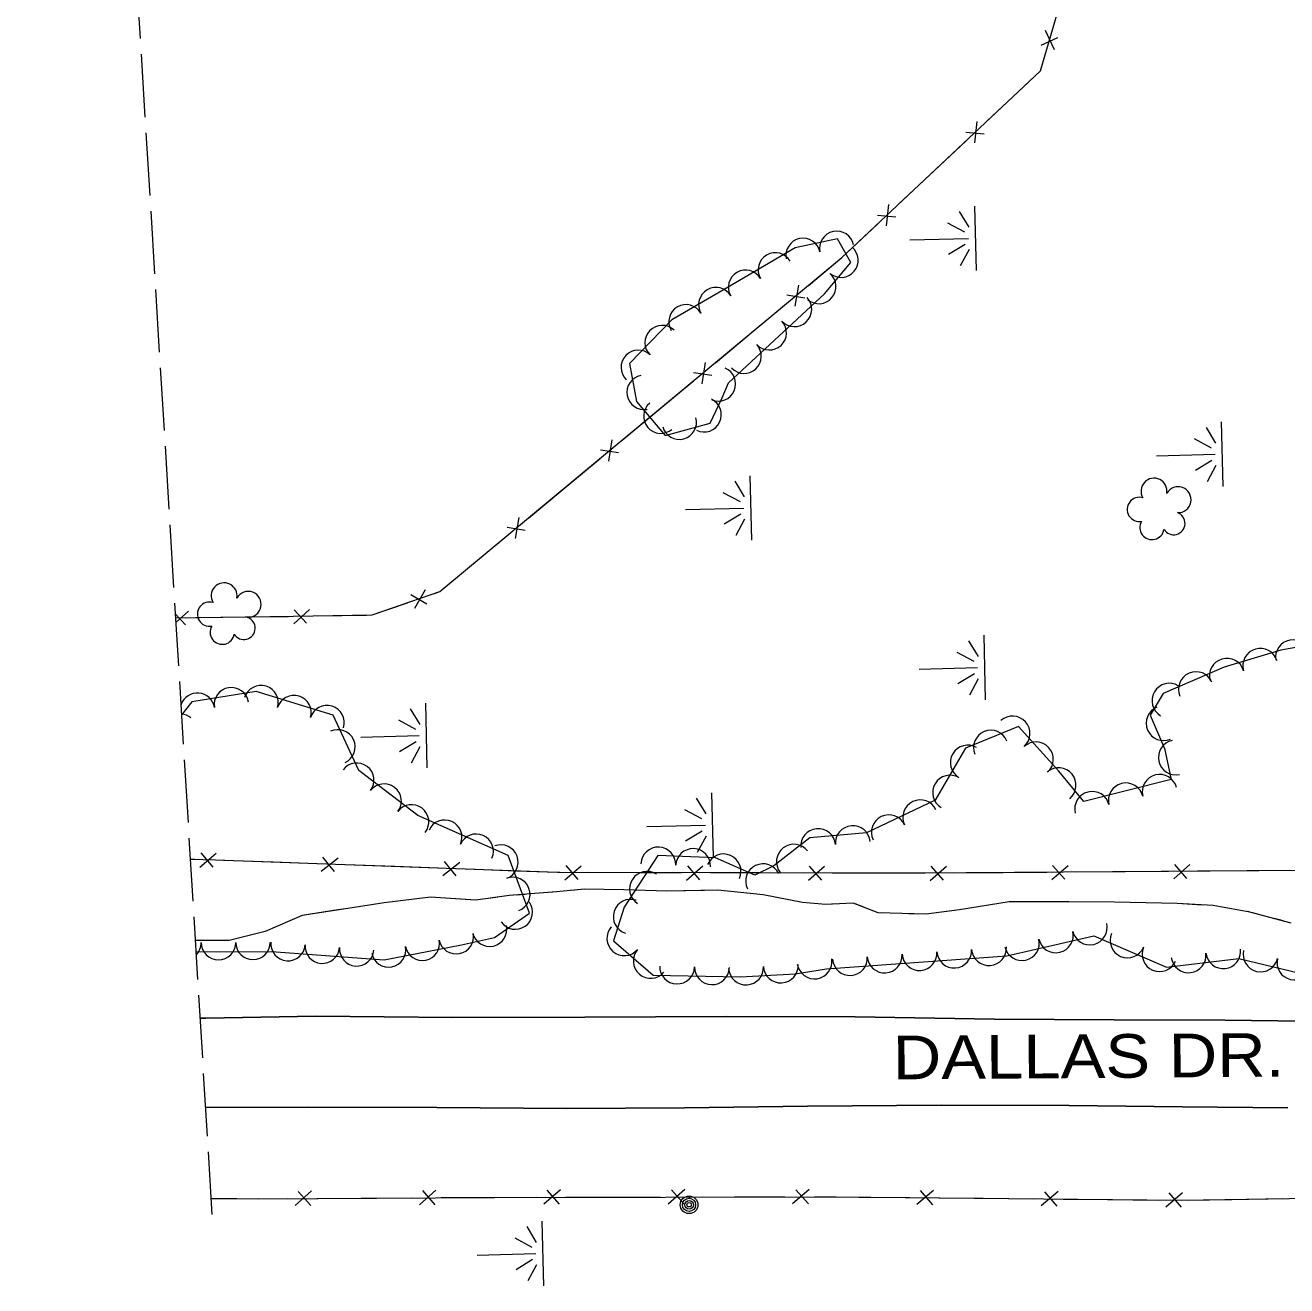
# Model space of a CAD drawing. Extents: x 296527 to 298902, y 45711 to 46924.
# Drawn here: x 297194.1 to 297483.2, y 45839.8 to 46128.6 of the extents above; entities that cross this region are included whole.
import ezdxf

# ---------------------------------------------------------------- set-up
doc = ezdxf.new("R2010")
doc.units = 0
doc.header["$LTSCALE"] = 2.4
doc.linetypes.add('LONG_DASHED', pattern=[7.5, 6, -1.5])
for name, color, linetype, lineweight in [('11', 7, 'Continuous', 25), ('14', 7, 'Continuous', 13), ('15', 7, 'Continuous', 13), ('18', 7, 'Continuous', 13), ('19', 7, 'Continuous', 13), ('4', 7, 'Continuous', 13)]:
    doc.layers.add(name, color=color, linetype=linetype, lineweight=lineweight)

msp = doc.modelspace()

# ---------------------------------------------------------------- linework, layer by layer
at = {"layer": '11'}
for points in [[(297692.464, 45930.163), (297690.32, 45923.952), (297684.827, 45916.459), (297679.112, 45910.524), (297672.63, 45905.391), (297667.252, 45902.536), (297659.261, 45901.182), (297651.908, 45900.829), (297627.018, 45900.926), (297601.742, 45901.264), (297574.823, 45900.95), (297549.818, 45900.747), (297522.046, 45900.557), (297493.301, 45900.343), (297469.091, 45900.673), (297443.631, 45900.721), (297416.195, 45900.841), (297384.328, 45901.413), (297354.714, 45901.501), (297322.333, 45901.303), (297291.974, 45901.295), (297260.71, 45901.545), (297235.442, 45901.114), (297234.199, 45901.096)], [(297483.461, 45880.583), (297459.317, 45880.818), (297433.334, 45881.104), (297403.984, 45881.155), (297373.398, 45880.941), (297345.189, 45880.52), (297318.243, 45880.415), (297288.435, 45880.613), (297258.683, 45880.74), (297235.449, 45880.63)]]:
    msp.add_lwpolyline(points, dxfattribs=at)
at = {"layer": '14'}
for centre, radius in [((297346.232, 45858.331), 2.018), ((297346.219, 45858.328), 1.518), ((297346.259, 45858.335), 1.008), ((297346.249, 45858.339), 0.502)]:
    msp.add_circle(centre, radius, dxfattribs=at)
at = {"layer": '15'}
for p, q in [((297426.934, 46124.06), (297430.755, 46125.839)), ((297429.983, 46122.984), (297427.935, 46127.452)), ((297414.481, 46106.639), (297422.703, 46114.371)), ((297411.731, 46101.673), (297412.218, 46106.563)), ((297402.47, 46095.342), (297409.701, 46102.143)), ((297409.643, 46104.141), (297413.839, 46103.748)), ((297394.249, 46087.61), (297402.47, 46095.342)), ((297391.499, 46082.644), (297391.986, 46087.535)), ((297389.41, 46085.112), (297393.607, 46084.719)), ((297382.238, 46076.314), (297389.469, 46083.114)), ((297370.56, 46064.254), (297371.347, 46069.105)), ((297360.927, 46058.506), (297368.563, 46064.848)), ((297368.627, 46066.846), (297372.791, 46066.195)), ((297352.245, 46051.295), (297360.927, 46058.506)), ((297349.194, 46046.507), (297349.982, 46051.359)), ((297339.561, 46040.759), (297347.197, 46047.102)), ((297347.262, 46049.099), (297351.426, 46048.449)), ((297330.879, 46033.548), (297339.561, 46040.759)), ((297327.829, 46028.761), (297328.616, 46033.612)), ((297325.896, 46031.353), (297330.06, 46030.702)), ((297318.196, 46023.013), (297325.832, 46029.355)), ((297309.514, 46015.801), (297318.196, 46023.013)), ((297306.463, 46011.014), (297307.251, 46015.866)), ((297304.531, 46013.606), (297308.695, 46012.955)), ((297296.83, 46005.266), (297304.466, 46011.609)), ((297282.489, 45998.157), (297286.154, 45996.076)), ((297283.381, 45995.049), (297285.833, 45999.309)), ((297228.547, 45993.677), (297230.783, 45991.208)), ((297228.659, 45991.846), (297231.489, 45994.379)), ((297233.209, 45992.907), (297244.494, 45993.057)), ((297244.494, 45993.057), (297254.42, 45993.189)), ((297255.605, 45991.471), (297259.256, 45994.762)), ((297255.721, 45994.703), (297258.561, 45991.589)), ((297260.981, 45993.296), (297272.266, 45993.486)), ((297231.975, 45937.535), (297232.952, 45937.51)), ((297234.07, 45935.74), (297237.873, 45938.89)), ((297234.321, 45938.979), (297237.041, 45935.734)), ((297239.542, 45937.325), (297250.873, 45936.915)), ((297261.937, 45934.773), (297265.774, 45937.88)), ((297262.224, 45938.008), (297264.908, 45934.733)), ((297290.109, 45937.001), (297292.793, 45933.726)), ((297250.873, 45936.915), (297260.839, 45936.555)), ((297267.426, 45936.317), (297278.757, 45935.908)), ((297278.757, 45935.908), (297288.723, 45935.547)), ((297289.822, 45933.765), (297293.659, 45936.872)), ((297295.311, 45935.309), (297306.642, 45934.9)), ((297317.767, 45932.814), (297321.496, 45936.05)), ((297317.944, 45936.057), (297320.737, 45932.875)), ((297323.201, 45934.544), (297334.539, 45934.519)), ((297334.539, 45934.519), (297344.512, 45934.498)), ((297345.67, 45932.753), (297349.399, 45935.989)), ((297345.847, 45935.997), (297348.64, 45932.815)), ((297351.104, 45934.483), (297362.442, 45934.459)), ((297362.442, 45934.459), (297372.415, 45934.437)), ((297373.573, 45932.693), (297377.302, 45935.929)), ((297373.75, 45935.937), (297376.543, 45932.755)), ((297379.007, 45934.423), (297390.345, 45934.398)), ((297401.492, 45932.661), (297405.191, 45935.931)), ((297401.639, 45935.906), (297404.462, 45932.75)), ((297406.91, 45934.441), (297418.248, 45934.521)), ((297418.248, 45934.521), (297428.22, 45934.592)), ((297429.394, 45932.859), (297433.094, 45936.129)), ((297429.541, 45936.104), (297432.364, 45932.948)), ((297434.812, 45934.639), (297446.15, 45934.719)), ((297446.15, 45934.719), (297456.122, 45934.789)), ((297457.296, 45933.056), (297460.996, 45936.326)), ((297457.444, 45936.301), (297460.266, 45933.145)), ((297462.714, 45934.836), (297474.052, 45934.916)), ((297474.052, 45934.916), (297484.025, 45934.987)), ((297345.241, 45861.814), (297341.443, 45858.493)), ((297373.751, 45861.855), (297369.952, 45858.535)), ((297242.582, 45859.676), (297236.727, 45859.695)), ((297259.705, 45861.509), (297255.921, 45858.173)), ((297259.55, 45858.194), (297256.671, 45861.422)), ((297271.092, 45859.795), (297260.902, 45859.736)), ((297282.676, 45859.861), (297271.092, 45859.795)), ((297288.215, 45861.673), (297284.43, 45858.336)), ((297288.06, 45858.357), (297285.18, 45861.586)), ((297299.601, 45859.958), (297289.412, 45859.9)), ((297316.732, 45861.772), (297312.933, 45858.452)), ((297316.563, 45858.457), (297313.697, 45861.698)), ((297328.111, 45860.009), (297317.921, 45859.994)), ((297339.696, 45860.026), (297328.111, 45860.009)), ((297345.072, 45858.499), (297342.206, 45861.74)), ((297356.62, 45860.051), (297346.431, 45860.036)), ((297368.205, 45860.068), (297356.62, 45860.051)), ((297373.582, 45858.541), (297370.716, 45861.781)), ((297396.714, 45859.92), (297385.13, 45860.034)), ((297402.28, 45861.645), (297398.444, 45858.368)), ((297402.073, 45858.333), (297399.244, 45861.605)), ((297413.638, 45859.754), (297403.449, 45859.854)), ((297425.223, 45859.64), (297413.638, 45859.754)), ((297430.788, 45861.365), (297426.952, 45858.088)), ((297430.582, 45858.053), (297427.752, 45861.326)), ((297442.146, 45859.474), (297431.958, 45859.574)), ((297453.731, 45859.36), (297442.146, 45859.474)), ((297459.297, 45861.085), (297455.461, 45857.808)), ((297459.09, 45857.773), (297456.261, 45861.046)), ((297470.654, 45859.492), (297460.466, 45859.33)), ((297482.237, 45859.677), (297470.654, 45859.492))]:
    msp.add_line(p, q, dxfattribs=at)
for points in [[(297231.975, 45937.535), (297237.679, 45937.392), (297316.078, 45934.559), (297398.392, 45934.381), (297521.626, 45935.253), (297609.523, 45938.083), (297665.677, 45942.947), (297668.427, 46057.646), (297669.182, 46140.171), (297668.204, 46219.412), (297669.512, 46293.511), (297671.894, 46387.823), (297670.956, 46464.804), (297671.697, 46515.594), (297656.944, 46523.338)], [(297228.598, 45992.845), (297255.591, 45993.205), (297273.582, 45993.508), (297289.114, 45998.857), (297381.272, 46075.405), (297426.761, 46118.188), (297430.618, 46131.261), (297429.398, 46171.469), (297427.319, 46237.747), (297423.718, 46327.93), (297419.87, 46420.715), (297418.884, 46474.114), (297419.946, 46500.671)], [(297422.703, 46114.371), (297426.761, 46118.188), (297427.993, 46122.365)], [(297373.61, 46069.041), (297381.272, 46075.405), (297382.238, 46076.314)], [(297287.927, 45998.448), (297289.114, 45998.857), (297296.83, 46005.266)], [(297272.266, 45993.486), (297273.582, 45993.508), (297281.723, 45996.312)], [(297306.642, 45934.9), (297316.078, 45934.559), (297316.609, 45934.558)], [(297390.345, 45934.398), (297398.392, 45934.381), (297400.318, 45934.395)], [(297641.689, 45859.135), (297548.298, 45860.728), (297459.061, 45859.308), (297379.941, 45860.085), (297301.626, 45859.97), (297247.591, 45859.66), (297236.727, 45859.695)], [(297254.167, 45859.698), (297247.591, 45859.66), (297242.582, 45859.676)], [(297311.186, 45859.984), (297301.626, 45859.97), (297299.601, 45859.958)], [(297385.13, 45860.034), (297379.941, 45860.085), (297374.941, 45860.078)]]:
    msp.add_lwpolyline(points, dxfattribs=at)
at = {"layer": '18'}
msp.add_lwpolyline([(297368.905, 46059.347), (297377.23, 46067.081), (297383.324, 46074.315), (297380.268, 46079.668), (297370.551, 46077.63), (297354.234, 46068.103), (297342.246, 46061.167), (297332.582, 46051.158), (297334.207, 46042.416), (297340.765, 46034.669), (297351.03, 46037.448), (297353.844, 46043.275), (297355.29, 46046.674)], close=True, dxfattribs=at)
for points in [[(297498.551, 45988.415), (297481.877, 45985.45), (297468.864, 45981.574), (297454.87, 45975.508), (297451.927, 45970.548), (297455.193, 45962.929), (297456.746, 45955.787), (297436.72, 45950.739), (297430.945, 45957.741), (297421.733, 45967.944), (297409.614, 45962.973), (297402.595, 45951.055), (297386.858, 45943.58), (297373.897, 45942.468), (297365.643, 45936.02), (297361.31, 45933.883), (297352.247, 45937.843), (297339.051, 45938.411), (297331.373, 45926.574), (297328.878, 45918.836), (297337.997, 45910.978), (297357.977, 45910.552), (297370.544, 45911.292), (297377.693, 45912.402), (297419.087, 45915.365), (297439.027, 45919.983), (297455.641, 45912.809), (297472.209, 45914.757), (297495.72, 45909.135)], [(297233.268, 45916.344), (297250.511, 45916.414), (297276.341, 45914.44), (297294.098, 45917.907), (297301.639, 45919.626), (297309.639, 45925.147), (297304.75, 45938.365), (297284.098, 45947.558), (297270.515, 45957.89), (297264.633, 45970.562), (297246.994, 45975.931), (297232.252, 45973.567), (297229.951, 45970.674)]]:
    msp.add_lwpolyline(points, dxfattribs=at)
for centre, radius, start, end in [((297372.355, 46075.899), 3.945, 11.85293, 191.8376), ((297380.077, 46077.518), 3.945, 11.85293, 191.8376), ((297365.997, 46072.58), 3.945, 30.28702, 210.27169), ((297381.038, 46074.806), 3.945, 229.89651, 49.88119), ((297359.184, 46068.602), 3.945, 30.28702, 210.27169), ((297375.955, 46068.772), 3.945, 229.89651, 49.88119), ((297352.357, 46064.631), 3.945, 30.06042, 210.04509), ((297345.528, 46060.68), 3.945, 30.06042, 210.04509), ((297370.39, 46063.545), 3.945, 222.90002, 42.8847), ((297340.055, 46055.925), 3.945, 46.01234, 225.99702), ((297364.611, 46058.171), 3.945, 222.95541, 42.94009), ((297334.575, 46050.249), 3.945, 46.01234, 225.99702), ((297358.836, 46052.796), 3.945, 222.95541, 42.94009), ((297352.95, 46046.449), 3.945, 246.96183, 66.94651), ((297335.921, 46044.497), 3.945, 100.53786, 280.52254), ((297339.761, 46039.051), 3.945, 130.25628, 310.24096), ((297349.671, 46039.383), 3.945, 244.23064, 64.21531), ((297343.987, 46037.68), 3.945, 195.15599, 15.14067), ((297452.772, 46021.881), 2.974, 349.94487, 211.17875), ((297458.288, 46019.921), 2.975, 267.59569, 150.56896), ((297449.412, 46017.687), 2.777, 72.91576, 280.68875), ((297457.281, 46014.491), 2.611, 212.30092, 70.23353), ((297452.328, 46013.55), 2.783, 149.59278, 350.60382), ((297239.661, 45997.885), 2.974, 349.94487, 211.17875), ((297245.177, 45995.925), 2.975, 267.59569, 150.56896), ((297236.301, 45993.691), 2.777, 72.91576, 280.68875), ((297244.17, 45990.495), 2.611, 212.30092, 70.23353), ((297239.217, 45989.554), 2.783, 149.59278, 350.60382), ((297484.634, 45983.817), 3.993, 10.0907, 190.07538), ((297469.494, 45979.581), 3.993, 16.59414, 196.57882), ((297477.147, 45981.86), 3.993, 16.59414, 196.57882), ((297462.4, 45976.494), 3.993, 23.44302, 203.4277), ((297456.318, 45973.853), 3.993, 59.32502, 239.3097), ((297233.533, 45971.679), 3.949, 9.11795, 160.55067), ((297241.33, 45972.93), 3.949, 9.11795, 189.10263), ((297248.142, 45973.421), 3.949, 343.07834, 163.06302), ((297255.697, 45971.122), 3.949, 343.07834, 163.06302), ((297263.251, 45968.822), 3.949, 343.07834, 163.06302), ((297454.992, 45968.704), 3.993, 113.21079, 293.19547), ((297229.557, 45966.856), 3.949, 51.51947, 84.36026), ((297420.363, 45966.342), 3.993, 312.08565, 132.07033), ((297265.74, 45963.269), 3.949, 294.90712, 114.89179), ((297415.388, 45963.083), 3.993, 22.31024, 202.29491), ((297410.095, 45959.671), 3.993, 59.51208, 239.49676), ((297425.715, 45960.415), 3.993, 312.08565, 132.07033), ((297457.788, 45960.834), 3.993, 102.27543, 282.26011), ((297270.066, 45955.635), 3.949, 322.74899, 142.73366), ((297430.921, 45954.486), 3.993, 309.52226, 129.50694), ((297276.351, 45950.854), 3.949, 322.74899, 142.73366), ((297406.042, 45952.79), 3.993, 59.51208, 239.49676), ((297446.337, 45951.008), 3.993, 14.1556, 194.14028), ((297454.081, 45952.96), 3.993, 14.1556, 194.14028), ((297438.594, 45949.056), 3.993, 14.1556, 194.14028), ((297282.636, 45946.074), 3.949, 322.74899, 142.73366), ((297399.209, 45947.133), 3.993, 25.41516, 205.39984), ((297290.229, 45942.566), 3.949, 336.01198, 155.99665), ((297391.995, 45943.706), 3.993, 25.41516, 205.39984), ((297297.444, 45939.355), 3.949, 336.01198, 155.99665), ((297375.801, 45940.534), 3.993, 4.91139, 184.89607), ((297383.758, 45941.216), 3.993, 4.91139, 184.89607), ((297303.096, 45936.88), 3.949, 290.30581, 110.29048), ((297339.168, 45936.314), 3.993, 357.54298, 177.52766), ((297347.147, 45935.971), 3.993, 357.54298, 177.52766), ((297370.255, 45936.971), 3.993, 38.00451, 217.98919), ((297354.132, 45934.738), 3.993, 336.40515, 156.38983), ((297336.572, 45930.748), 3.993, 57.03844, 237.02312), ((297363.19, 45932.48), 3.993, 26.2598, 206.24448), ((297305.835, 45929.473), 3.949, 290.30581, 110.29048), ((297332.854, 45924.357), 3.993, 72.13654, 252.12121), ((297306.392, 45925.417), 3.949, 214.61819, 34.60287), ((297438.065, 45921.906), 3.993, 193.04718, 13.03186), ((297292.86, 45919.771), 3.949, 191.0555, 11.04018), ((297300.501, 45921.486), 3.949, 192.84903, 12.83371), ((297331.387, 45919.433), 3.993, 139.25562, 319.24029), ((297430.286, 45920.104), 3.993, 193.04718, 13.03186), ((297446.725, 45918.935), 3.993, 156.65276, 336.63744), ((297230.469, 45918.399), 3.949, 316.02016, 0.22597), ((297238.365, 45918.431), 3.949, 180.24129, 0.22597), ((297246.262, 45918.463), 3.949, 180.24129, 0.22597), ((297254.314, 45918.196), 3.949, 175.63746, 355.62213), ((297262.188, 45917.594), 3.949, 175.63746, 355.62213), ((297270.061, 45916.993), 3.949, 175.63746, 355.62213), ((297277.359, 45916.745), 3.949, 191.0555, 11.04018), ((297285.109, 45918.258), 3.949, 191.0555, 11.04018), ((297337.436, 45914.22), 3.993, 139.25562, 319.24029), ((297406.99, 45916.595), 3.993, 184.10193, 4.08661), ((297414.956, 45917.165), 3.993, 184.10193, 4.08661), ((297422.506, 45918.302), 3.993, 193.04718, 13.03186), ((297454.057, 45915.77), 3.993, 156.65276, 336.63744), ((297468.649, 45916.443), 3.993, 186.71349, 6.69816), ((297374.98, 45914.096), 3.993, 188.8333, 8.81798), ((297383.094, 45914.884), 3.993, 184.10193, 4.08661), ((297391.06, 45915.454), 3.993, 184.10193, 4.08661), ((297399.025, 45916.024), 3.993, 184.10193, 4.08661), ((297460.718, 45915.51), 3.993, 186.71349, 6.69816), ((297477.214, 45915.709), 3.993, 166.5595, 346.54417), ((297484.981, 45913.852), 3.993, 166.5595, 346.54417), ((297343.485, 45912.952), 3.993, 178.78623, 358.7709), ((297351.468, 45912.781), 3.993, 178.78623, 358.7709), ((297359.283, 45912.723), 3.993, 183.3776, 3.36228), ((297367.255, 45913.192), 3.993, 183.3776, 3.36228)]:
    msp.add_arc(centre, radius, start, end, dxfattribs=at)
at = {"layer": '19'}
for p, q in [((297408.149, 46085.974), (297410.332, 46082.344)), ((297412.07, 46072.43), (297411.694, 46087.22)), ((297409.426, 46081.22), (297405.521, 46083.322)), ((297396.816, 46079.47), (297410.232, 46079.81)), ((297409.497, 46078.416), (297405.704, 46076.119)), ((297408.464, 46073.603), (297410.459, 46077.34)), ((297464.7, 46036.484), (297466.883, 46032.854)), ((297468.621, 46022.94), (297468.245, 46037.73)), ((297465.977, 46031.73), (297462.072, 46033.832)), ((297453.367, 46029.98), (297466.783, 46030.32)), ((297466.048, 46028.926), (297462.255, 46026.629)), ((297465.015, 46024.113), (297467.01, 46027.85)), ((297356.703, 46024.175), (297358.886, 46020.545)), ((297360.624, 46010.631), (297360.248, 46025.421)), ((297357.98, 46019.421), (297354.075, 46021.523)), ((297345.37, 46017.671), (297358.786, 46018.011)), ((297358.051, 46016.617), (297354.258, 46014.32)), ((297357.018, 46011.804), (297359.013, 46015.541)), ((297410.279, 45987.593), (297412.462, 45983.963)), ((297414.2, 45974.049), (297413.824, 45988.839)), ((297411.556, 45982.839), (297407.651, 45984.941)), ((297398.946, 45981.089), (297412.362, 45981.429)), ((297411.627, 45980.035), (297407.834, 45977.738)), ((297410.594, 45975.222), (297412.589, 45978.959)), ((297282.313, 45972.021), (297284.496, 45968.391)), ((297286.234, 45958.477), (297285.858, 45973.267)), ((297283.59, 45967.267), (297279.685, 45969.369)), ((297270.98, 45965.517), (297284.396, 45965.857)), ((297283.661, 45964.463), (297279.868, 45962.166)), ((297282.628, 45959.65), (297284.623, 45963.387)), ((297347.879, 45951.527), (297350.062, 45947.897)), ((297351.8, 45937.983), (297351.424, 45952.773)), ((297349.156, 45946.773), (297345.251, 45948.875)), ((297336.546, 45945.023), (297349.962, 45945.363)), ((297349.227, 45943.969), (297345.434, 45941.672)), ((297348.194, 45939.156), (297350.189, 45942.893)), ((297302.379, 45928.834), (297300.289, 45928.551)), ((297308.673, 45929.468), (297306.57, 45929.306)), ((297314.982, 45929.954), (297312.879, 45929.792)), ((297386.241, 45926.531), (297384.268, 45927.275)), ((297470.097, 45926.238), (297468.02, 45926.6)), ((297392.339, 45925.185), (297390.231, 45925.256)), ((297398.664, 45924.973), (297396.556, 45925.043)), ((297482.416, 45923.389), (297480.377, 45923.931)), ((297309.01, 45853.326), (297311.193, 45849.696)), ((297312.931, 45839.782), (297312.555, 45854.572)), ((297310.287, 45848.572), (297306.382, 45850.674)), ((297297.677, 45846.822), (297311.093, 45847.162)), ((297310.358, 45845.768), (297306.565, 45843.471)), ((297309.325, 45840.955), (297311.32, 45844.692))]:
    msp.add_line(p, q, dxfattribs=at)
for points in [[(297484.248, 45922.901), (297474.774, 45925.422), (297466.373, 45926.887), (297458.124, 45927.356), (297443.744, 45927.668), (297430.165, 45927.771), (297419.605, 45927.736), (297408.17, 45925.907), (297400.528, 45924.91), (297389.566, 45925.278), (297383.852, 45927.432), (297377.602, 45927.162), (297372.198, 45927.58), (297363.174, 45929.385), (297352.838, 45930.419), (297341.148, 45930.216), (297331.27, 45930.493), (297322.222, 45930.674), (297315.854, 45930.021), (297304.965, 45929.183), (297297.32, 45928.15), (297286.983, 45928.867), (297276.332, 45927.562), (297268.041, 45926.263), (297257.587, 45924.658), (297249.073, 45920.941), (297240.826, 45918.921), (297233.11, 45918.94)], [(297296.1, 45928.235), (297286.983, 45928.867), (297276.332, 45927.562), (297268.041, 45926.263), (297265.743, 45925.91)], [(297349.745, 45930.365), (297341.148, 45930.216), (297331.27, 45930.493), (297322.222, 45930.674), (297319.181, 45930.362)], [(297380.081, 45927.269), (297377.602, 45927.162), (297372.198, 45927.58), (297363.174, 45929.385), (297352.838, 45930.419), (297349.745, 45930.365)], [(297265.743, 45925.91), (297257.587, 45924.658), (297249.073, 45920.941), (297240.826, 45918.921), (297236.272, 45918.932)], [(297433.257, 45927.748), (297430.165, 45927.771), (297419.605, 45927.736), (297408.17, 45925.907), (297402.862, 45925.214)], [(297463.83, 45927.032), (297458.124, 45927.356), (297443.744, 45927.668), (297433.257, 45927.748)], [(297476.301, 45925.016), (297474.774, 45925.422), (297474.252, 45925.513)]]:
    msp.add_lwpolyline(points, dxfattribs=at)
at = {"layer": '4', "linetype": 'LONG_DASHED'}
msp.add_lwpolyline([(297236.947, 45856.087), (297194.081, 46558.227), (297396.47, 46901.483)], dxfattribs=at)

# ---------------------------------------------------------------- texts
at = {"layer": '11', "width": 1.15}
msp.add_text('DALLAS DR.', height=10, rotation=0.401, dxfattribs=at).set_placement((297392.943, 45887.078))

doc.saveas('drawing.dxf')
